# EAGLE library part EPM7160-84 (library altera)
EPM7160E MAX 7000 family
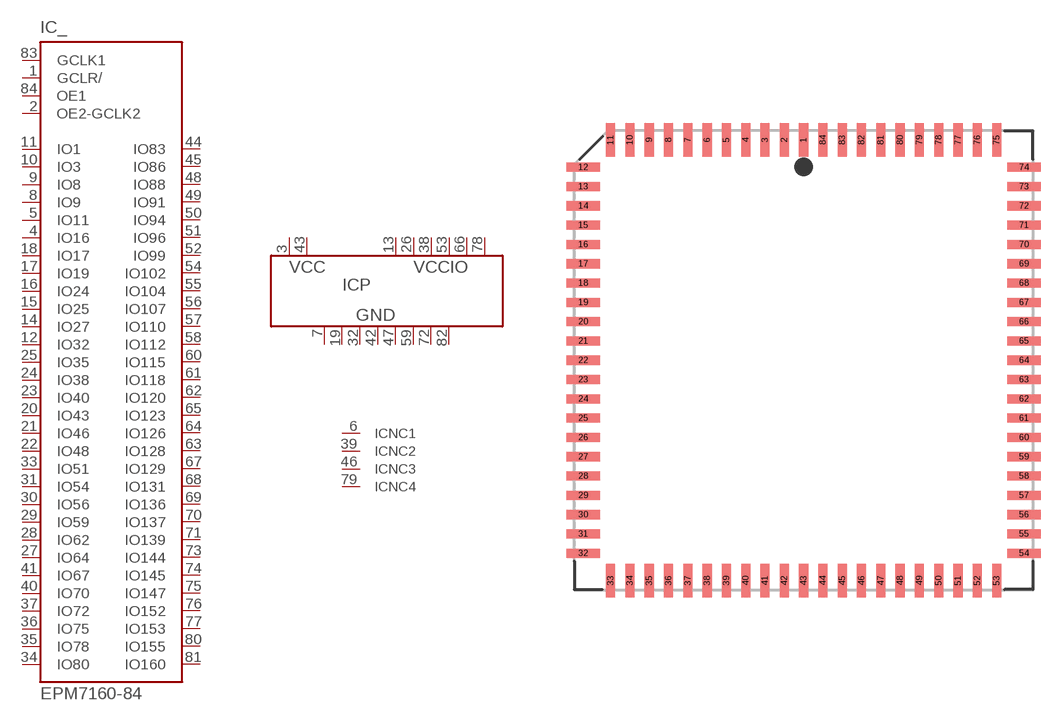
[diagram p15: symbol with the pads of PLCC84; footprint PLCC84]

Designator prefix IC; gates _=7160-J84 P=PWR8-2-6 NC1=NC NC2=NC NC3=NC NC4=NC

## EPM7160-84 (MPN: EPM7160SLC84-10N; OC_FARNELL: 1549460; OC_NEWARK: 51R0533)  [PLCC84]
1  _:GCLR/  in
2  _:OE2-GCLK2  in
3  P:VCC  pwr
4  _:IO16
5  _:IO11
6  NC1:NC  nc
7  P:GND  pwr
8  _:IO9
9  _:IO8
10  _:IO3
11  _:IO1
12  _:IO32
13  P:VCCIO  pwr
14  _:IO27
15  _:IO25
16  _:IO24
17  _:IO19
18  _:IO17
19  P:GND  pwr
20  _:IO43
21  _:IO46
22  _:IO48
23  _:IO40
24  _:IO38
25  _:IO35
26  P:VCCIO  pwr
27  _:IO64
28  _:IO62
29  _:IO59
30  _:IO56
31  _:IO54
32  P:GND  pwr
33  _:IO51
34  _:IO80
35  _:IO78
36  _:IO75
37  _:IO72
38  P:VCCIO  pwr
39  NC2:NC  nc
40  _:IO70
41  _:IO67
42  P:GND  pwr
43  P:VCC  pwr
44  _:IO83
45  _:IO86
46  NC3:NC  nc
47  P:GND  pwr
48  _:IO88
49  _:IO91
50  _:IO94
51  _:IO96
52  _:IO99
53  P:VCCIO  pwr
54  _:IO102
55  _:IO104
56  _:IO107
57  _:IO110
58  _:IO112
59  P:GND  pwr
60  _:IO115
61  _:IO118
62  _:IO120
63  _:IO128
64  _:IO126
65  _:IO123
66  P:VCCIO  pwr
67  _:IO129
68  _:IO131
69  _:IO136
70  _:IO137
71  _:IO139
72  P:GND  pwr
73  _:IO144
74  _:IO145
75  _:IO147
76  _:IO152
77  _:IO153
78  P:VCCIO  pwr
79  NC4:NC  nc
80  _:IO155
81  _:IO160
82  P:GND  pwr
83  _:GCLK1  in
84  _:OE1  in

## Footprint PLCC84 (pad centres in mm)
Plastic J-Lead Chip Carrier
smd 0.6 x 2.2: 1 0,14.5; 2 -1.27,14.5; 3 -2.54,14.5; 4 -3.81,14.5; 5 -5.08,14.5; 6 -6.35,14.5; 7 -7.62,14.5; 8 -8.89,14.5; 9 -10.16,14.5; 10 -11.43,14.5; 11 -12.7,14.5; 33 -12.7,-14.5; 34 -11.43,-14.5; 35 -10.16,-14.5; 36 -8.89,-14.5; 37 -7.62,-14.5; 38 -6.35,-14.5; 39 -5.08,-14.5; 40 -3.81,-14.5; 41 -2.54,-14.5; 42 -1.27,-14.5; 43 0,-14.5; 44 1.27,-14.5; 45 2.54,-14.5; 46 3.81,-14.5; 47 5.08,-14.5; 48 6.35,-14.5; 49 7.62,-14.5; 50 8.89,-14.5; 51 10.16,-14.5; 52 11.43,-14.5; 53 12.7,-14.5; 75 12.7,14.5; 76 11.43,14.5; 77 10.16,14.5; 78 8.89,14.5; 79 7.62,14.5; 80 6.35,14.5; 81 5.08,14.5; 82 3.81,14.5; 83 2.54,14.5; 84 1.27,14.5
smd 2.2 x 0.6: 12 -14.5,12.7; 13 -14.5,11.43; 14 -14.5,10.16; 15 -14.5,8.89; 16 -14.5,7.62; 17 -14.5,6.35; 18 -14.5,5.08; 19 -14.5,3.81; 20 -14.5,2.54; 21 -14.5,1.27; 22 -14.5,0; 23 -14.5,-1.27; 24 -14.5,-2.54; 25 -14.5,-3.81; 26 -14.5,-5.08; 27 -14.5,-6.35; 28 -14.5,-7.62; 29 -14.5,-8.89; 30 -14.5,-10.16; 31 -14.5,-11.43; 32 -14.5,-12.7; 54 14.5,-12.7; 55 14.5,-11.43; 56 14.5,-10.16; 57 14.5,-8.89; 58 14.5,-7.62; 59 14.5,-6.35; 60 14.5,-5.08; 61 14.5,-3.81; 62 14.5,-2.54; 63 14.5,-1.27; 64 14.5,0; 65 14.5,1.27; 66 14.5,2.54; 67 14.5,3.81; 68 14.5,5.08; 69 14.5,6.35; 70 14.5,7.62; 71 14.5,8.89; 72 14.5,10.16; 73 14.5,11.43; 74 14.5,12.7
